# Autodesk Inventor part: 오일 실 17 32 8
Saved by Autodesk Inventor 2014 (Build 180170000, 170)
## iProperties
Created: 2026-05
Part Number: 오일 실 17 32 8
Material: 일반
Document SubType Name: Modeling
Designer: dg
Density: 1 g/cm^3
Appearance: 기본값
Author: dg
Author: jhkim
Description: 오일-실
Creation Date: 2026-04-27
Sending System: Autodesk Inventor 2027
Preprocessor: ST-DEVELOPER v20.1
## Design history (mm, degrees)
node "오일 실 17 32 81"
body "Solid1"
node "기준1"
